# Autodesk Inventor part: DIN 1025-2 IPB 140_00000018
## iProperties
Created: 2006-02
Part Number: DIN 1025-2 IPB 140_00000018
Material: Default
Document SubType Name: Modeling
Designer: 40664
Manufacturer: Standard
Standards Organization: Custom
Stock Number: DIN 1025-2 IPB 140
Mass: 14905.7 g
Surface Area: 28033.2 cm^2
Volume: 14905.7 cm^3
Density: 1 g/cm^3
G_L: 3470.000 mm
G_W: 140.000 mm
G_H: 140.000 mm
AFG_Item: IPB 140
CSToolsMass: 15.0
CSToolsVolume: 14905705.0
CSToolsArea: 28033.0
Author: 40664
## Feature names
1. AFG_Detailed_DIN 1025-2 IPB 140_00000018 [Extrusion]
2. AFG_Simplified_DIN 1025-2 IPB 140_00000018 [Extrusion]
